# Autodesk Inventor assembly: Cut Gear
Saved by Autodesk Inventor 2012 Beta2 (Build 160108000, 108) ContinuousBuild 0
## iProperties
Created: 2011-01
Part Number: Cut Gear
Document SubType Name: Assembly
Designer: Beta-8540w
Categories: <?xml version="1.0" encoding="UTF-16"?> <MemberInstance><Categories><FamilyTemplate/><ParamToTemplateMap><ParamToTemplate><ParamToTemplate CategoryParameter="//
ClientObjectVersion: 1
Author: Beta-8540w
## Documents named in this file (1)
- C:\Inventor 2012 Essentials\Assemblies\Chapter 8\Design Accelerators\Cut Gear c08-03.iam
